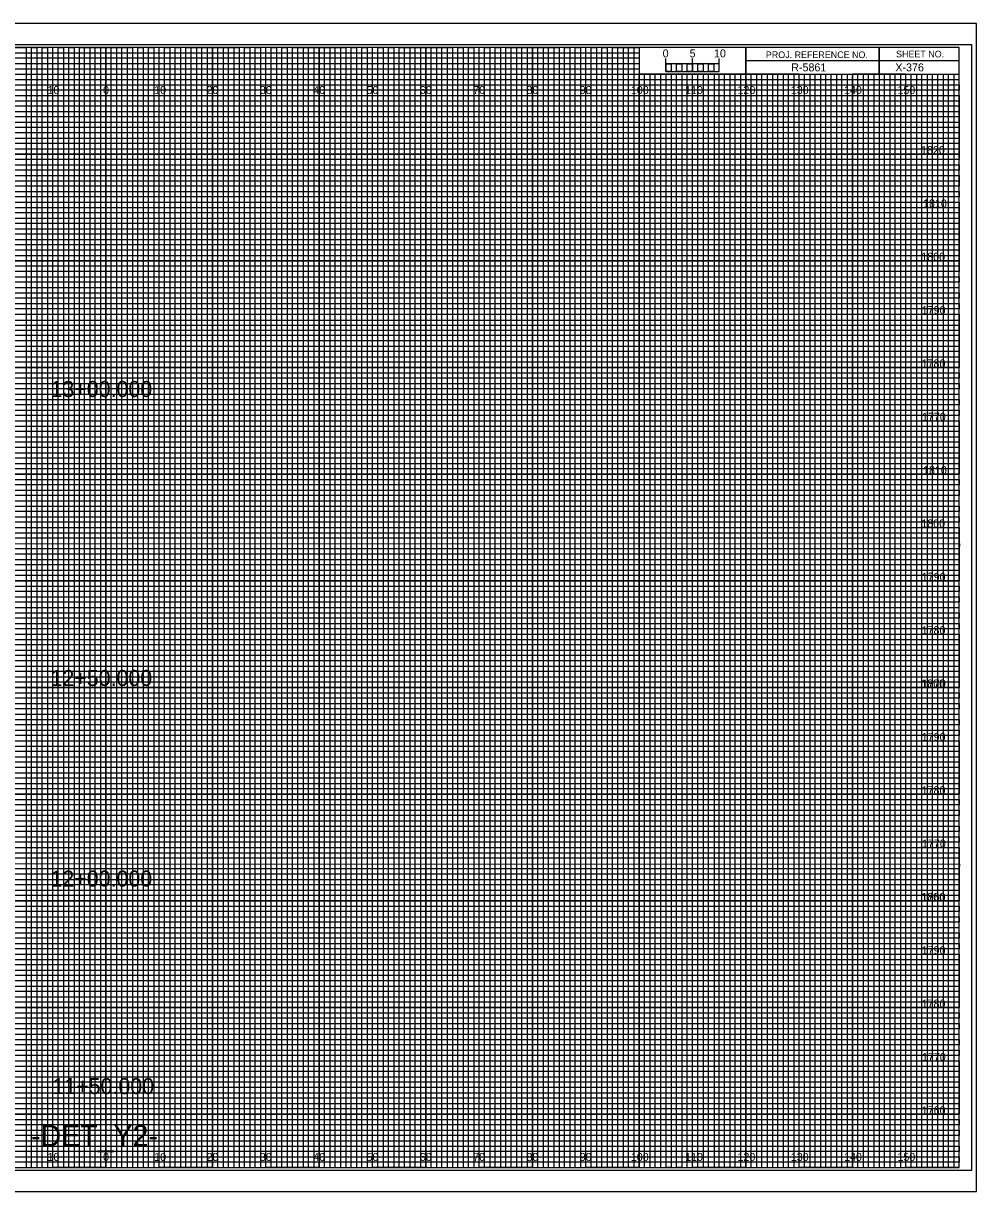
# Model space of a CAD drawing. Extents: x -13 to 323, y -5 to 874.
# Drawn here: x 144.5 to 323.3, y 215.5 to 434.5 of the extents above; entities that cross this region are included whole.
import ezdxf

# ---------------------------------------------------------------- set-up
doc = ezdxf.new("R2010")
doc.units = 0
for name, color, linetype in [('Prop Horizontal Alignment', 7, 'Continuous'), ('Prop XS Alignment Label', 7, 'Continuous'), ('Prop XS Bar Scale Labels', 7, 'Continuous'), ('Prop XS Earthwork Shape', 7, 'Continuous'), ('Prop XS Project Number', 7, 'Continuous'), ('Prop XS Sheet Number', 7, 'Continuous'), ('Raster_Level_0', 7, 'Continuous'), ('Scratch_Level_3', 7, 'Continuous'), ('Sheet Cross Section CELL', 7, 'Continuous'), ('Sheet Cross Section Grid Middle CELL', 7, 'Continuous'), ('Sheet Cross Section Grid Minor 1 CELL', 7, 'Continuous'), ('Sheet Cross Section Grid Minor 2 CELL', 7, 'Continuous'), ('Sheet Cross Section Scale CELL', 7, 'Continuous'), ('Sheet Cutting Line CELL', 7, 'Continuous'), ('Sheet DOT Grid CELL', 7, 'Continuous'), ('Sheet Plot Border Inside CELL', 7, 'Continuous'), ('Sheet Plot Border Outside CELL', 7, 'Continuous')]:
    doc.layers.add(name, color=color, linetype=linetype)

msp = doc.modelspace()

# ---------------------------------------------------------------- linework, layer by layer
at = {"layer": 'Prop XS Earthwork Shape'}
for p, q in [((150, 430), (140, 430)), ((150, 220), (150, 430)), ((170, 430), (160, 430)), ((160, 430), (160, 220)), ((170, 220), (170, 430)), ((190, 430), (180, 430)), ((180, 430), (180, 220)), ((190, 220), (190, 430)), ((210, 430), (200, 430)), ((200, 430), (200, 220)), ((210, 220), (210, 430)), ((230, 430), (220, 430)), ((220, 430), (220, 220)), ((230, 220), (230, 430)), ((250, 430), (240, 430)), ((240, 430), (240, 220)), ((250, 220), (250, 430)), ((260, 430), (260, 220)), ((270, 220), (270, 425)), ((290, 425), (280, 425)), ((280, 425), (280, 220)), ((290, 220), (290, 425)), ((310, 425), (300, 425)), ((300, 425), (300, 220)), ((310, 220), (310, 425)), ((160, 220), (150, 220)), ((180, 220), (170, 220)), ((200, 220), (190, 220)), ((220, 220), (210, 220)), ((240, 220), (230, 220)), ((260, 220), (250, 220)), ((280, 220), (270, 220)), ((300, 220), (290, 220)), ((320, 220), (310, 220)), ((320, 220), (320, 220))]:
    msp.add_line(p, q, dxfattribs=at)
for points in [[(0, 420), (320, 420), (320, 410), (0, 410)], [(0, 400), (320, 400), (320, 390), (0, 390)], [(0, 380), (320, 380), (320, 370), (0, 370)], [(0, 360), (320, 360), (320, 350), (0, 350)], [(0, 340), (320, 340), (320, 330), (0, 330)], [(0, 320), (320, 320), (320, 310), (0, 310)], [(0, 300), (320, 300), (320, 290), (0, 290)], [(0, 280), (320, 280), (320, 270), (0, 270)], [(0, 260), (320, 260), (320, 250), (0, 250)], [(0, 240), (320, 240), (320, 230), (0, 230)]]:
    msp.add_lwpolyline(points, dxfattribs=at)
at = {"layer": 'Sheet Cross Section CELL'}
for p, q in [((305, 430), (305, 425)), ((305, 425), (305, 430)), ((280, 427.5), (280, 425)), ((320, 427.49), (280, 427.49)), ((280, 425), (320, 425))]:
    msp.add_line(p, q, dxfattribs=at)
for points in [[(320, 430), (0, 430), (0, 220), (320, 220)], [(280, 430), (260, 430), (260, 425.03), (280, 425.03)], [(320, 430), (280, 430), (280, 425), (320, 425)]]:
    msp.add_lwpolyline(points, close=True, dxfattribs=at)
at = {"layer": 'Sheet Cross Section Grid Middle CELL'}
for points in [[(135, 430), (145, 430), (145, 220), (155, 220), (155, 430), (165, 430), (165, 220), (175, 220), (175, 430), (185, 430), (185, 220), (195, 220), (195, 430), (205, 430), (205, 220), (215, 220), (215, 430), (225, 430), (225, 220), (235, 220), (235, 430), (245, 430), (245, 220), (255, 220), (255, 430), (259.93, 430), (260, 430), (260, 425), (264.99, 425), (264.99, 220), (275, 220), (275, 425), (285, 425), (285, 220), (295, 220), (295, 425), (305, 425), (305, 220), (315, 220), (315, 425)], [(0, 425), (275, 425)], [(0, 405), (320, 405), (320, 415), (0, 415)], [(0, 385), (320, 385), (320, 395), (0, 395)], [(0, 365), (320, 365), (320, 375), (0, 375)], [(0, 345), (320, 345), (320, 355), (0, 355)], [(0, 325), (320, 325), (320, 335), (0, 335)], [(0, 305), (320, 305), (320, 315), (0, 315)], [(0, 285), (320, 285), (320, 295), (0, 295)], [(0, 265), (320, 265), (320, 275), (0, 275)], [(0, 245), (320, 245), (320, 255), (0, 255)], [(0, 225), (320, 225), (320, 235), (0, 235)]]:
    msp.add_lwpolyline(points, dxfattribs=at)
at = {"layer": 'Sheet Cross Section Grid Minor 1 CELL'}
for p, q in [((0, 429), (260, 429)), ((260, 427.98), (0, 427.98)), ((260, 429), (260, 427.98)), ((0, 427), (260, 427)), ((260, 425.89), (0, 425.89)), ((260, 427), (260, 425.89)), ((0, 424), (320, 424))]:
    msp.add_line(p, q, dxfattribs=at)
for points in [[(0, 423), (270, 423), (320, 423), (320, 422), (0, 422)], [(0, 421), (320, 421), (320, 419), (0, 419)], [(0, 418), (320, 418), (320, 417), (0, 416.98)], [(0, 416), (320, 416), (320, 414), (0, 414)], [(0, 413), (320, 413), (320, 412), (0, 412)], [(0, 411), (320, 411), (320, 409), (0, 409)], [(0, 408), (320, 408), (320, 407), (0, 407)], [(0, 406), (320, 406), (320, 404), (0, 404)], [(0, 403), (320, 403), (320, 402), (0, 402)], [(0, 401), (320, 401), (320, 399), (0, 399)], [(0, 398), (320, 398), (320, 397), (0, 397)], [(0, 396), (320, 396), (320, 393.95), (320, 393), (320, 392), (0, 392)], [(0, 394), (320, 394), (320, 393), (0, 393)], [(0, 391), (320, 391), (320, 389), (0, 389.03)], [(0, 389.03), (320, 389), (320, 388), (0, 388)], [(0, 387), (320, 387), (320, 386), (0, 386)], [(0, 384), (320, 384), (320, 383), (0, 383)], [(0, 382), (320, 382), (320, 381), (0, 381)], [(-0.07, 378.89), (320, 378.89), (320, 377.88), (-0.07, 377.88)], [(0, 377), (320, 377), (320, 376), (0, 376)], [(0, 374), (320, 374), (320, 373), (0, 373)], [(0, 372), (320, 372), (320, 371), (0, 371)], [(0, 369), (320, 369), (320, 368), (0, 368)], [(0, 367), (320, 367), (320, 366), (0, 366)], [(0, 364), (320, 364), (320, 363), (0, 363)], [(0, 362), (320, 362), (320, 361), (0, 361)], [(0, 359), (320, 359), (319.99, 357.98), (0, 358)], [(0, 357), (320, 357), (320, 356), (0, 356)], [(0, 354), (320, 354), (320, 353), (0, 353)], [(0, 352), (320, 352), (320, 351), (0, 351)], [(0, 349), (320, 349), (320, 348), (0, 348)], [(0, 347), (320, 347), (320, 346), (0, 346)], [(0, 344), (320, 344), (320, 343), (0, 343)], [(0, 342), (320, 342), (320, 341), (0, 341)], [(0, 339), (320, 339), (320, 338), (0, 338)], [(0, 336.99), (320.07, 336.91), (320, 336), (0, 336)], [(0, 334), (320, 334), (320, 333), (0, 333)], [(0, 332), (320, 332), (320, 331), (0, 331)], [(0, 329), (320, 329), (320, 328), (0, 328)], [(0, 327), (320, 327), (320, 326), (0, 326)], [(0, 324), (320, 324), (320, 323), (0, 323)], [(0, 322), (320, 322), (320, 321), (0, 321)], [(0, 319), (320, 319), (320, 318), (0, 318)], [(0, 317), (320, 317), (320, 316), (0, 316)], [(0, 314), (320, 314), (320, 313), (0, 313)], [(0, 312), (320, 312), (320, 311), (0, 311)], [(0, 309), (320, 309), (320, 308), (0, 308)], [(0, 307), (320, 307), (320, 306), (0, 306)], [(0, 304), (320, 304), (320, 303), (0, 303)], [(0, 302), (320, 302), (320, 301), (0, 301)], [(0, 299), (320, 299), (319.99, 297.98), (0, 298)], [(0, 297), (320, 297), (320, 296), (0, 296)], [(0, 294), (320, 294), (320, 293), (0, 293)], [(0, 292), (320, 292), (320, 291), (0, 291)], [(0, 289), (320, 289), (320, 288), (0, 288)], [(0, 287), (320, 287), (320, 286), (0, 286)], [(0, 284), (320, 284), (320, 283), (0, 283)], [(0, 282), (320, 282), (320, 281), (0, 281)], [(0, 279), (320, 279), (320, 278), (0, 278)], [(0, 276.99), (320.07, 276.91), (320, 276), (0, 276)], [(0, 274), (320, 274), (320, 273), (0, 273)], [(0, 272), (320, 272), (320, 271), (0, 271)], [(0, 269), (320, 269), (320, 268), (0, 268)], [(0, 267), (320, 267), (320, 266), (0, 266)], [(0, 264), (320, 264), (320, 263), (0, 263)], [(0, 262), (320, 262), (320, 261), (0, 261)], [(0, 259), (320, 259), (320, 258), (0, 258)], [(0, 257), (320, 257), (320, 256), (0, 256)], [(0, 254), (320, 254), (320, 253), (0, 253)], [(0, 252), (320, 252), (320, 251), (0, 251)], [(0, 249), (320, 249), (320, 248), (0, 248)], [(0, 247), (320, 247), (320, 246), (0, 246)], [(0, 244), (320, 244), (320, 243), (0, 243)], [(0, 242), (320, 242), (320, 241), (0, 241)], [(0, 239), (320, 239), (320, 238), (0, 238)], [(0, 237), (320, 237), (320, 236), (0, 236)], [(0, 234), (320, 234), (320, 233), (0, 233)], [(0, 232), (320, 232), (320, 231), (0, 231)], [(0, 229), (320, 229), (320, 228), (0, 228)], [(0, 227), (320, 227), (320, 226), (0, 226)], [(0, 224), (320, 224), (320, 223), (0, 223)], [(0, 222), (320, 222), (320, 221), (0, 221)]]:
    msp.add_lwpolyline(points, dxfattribs=at)
at = {"layer": 'Sheet Cross Section Grid Minor 2 CELL'}
for p, q in [((267, 425), (266.01, 425)), ((266.01, 425), (266.01, 220)), ((267, 220), (267, 425)), ((269, 425), (268, 425)), ((268, 425), (268, 220)), ((269, 220), (269, 425)), ((266.01, 220), (265, 220)), ((268, 220), (267, 220))]:
    msp.add_line(p, q, dxfattribs=at)
for points in [[(145, 220), (146, 220), (146, 430), (147, 430), (147, 220)], [(147, 220), (148, 220), (148, 430), (149, 430), (149, 220)], [(150, 220), (151, 220), (151, 430), (152, 430), (152, 220)], [(152, 220), (153, 220), (153, 430), (154, 430), (154, 220)], [(155, 220), (156, 220), (156, 430), (157, 430), (157, 220)], [(157, 220), (158, 220), (158, 430), (159, 430), (159, 220)], [(160, 220), (161, 220), (161, 430), (162, 430), (162, 220)], [(162, 220), (163, 220), (163, 430), (164, 430), (164, 220)], [(165, 220), (166, 220), (166, 430), (167, 430), (167, 220)], [(167, 220), (168, 220), (168, 430), (169, 430), (169, 220)], [(170, 220), (171, 220), (171, 430), (172, 430), (172, 220)], [(172, 220), (173, 220), (173, 430), (174, 430), (174, 220)], [(175, 220), (176, 220), (176, 430), (177, 430), (177, 220)], [(177, 220), (178, 220), (178, 430), (179, 430), (179, 220)], [(180, 220), (181, 220), (181, 430), (182, 430), (182, 220)], [(182, 220), (183, 220), (183, 430), (184, 430), (184, 220)], [(185, 220), (186, 220), (186, 430), (187, 430), (187, 220)], [(187, 220), (188, 220), (188, 430), (189, 430), (189, 220)], [(190, 220), (191, 220), (191, 430), (192, 430), (192, 220)], [(192, 220), (193, 220), (193, 430), (194, 430), (194, 220)], [(195, 220), (196, 220), (196, 430), (197, 430), (197, 220)], [(197, 220), (198, 220), (198, 430), (199, 430), (199, 220)], [(200, 220), (201, 220), (201, 430), (202, 430), (202, 220)], [(202, 220), (203, 220), (203, 430), (204, 430), (204, 220)], [(205, 220), (206, 220), (206, 430), (207, 430), (207, 220)], [(207, 220), (208, 220), (208, 430), (209, 430), (209, 220)], [(210, 220), (211, 220), (211, 430), (212, 430), (212, 220)], [(212, 220), (213, 220), (213, 430), (214, 430), (214, 220)], [(215, 220), (216, 220), (216, 430), (217, 430), (217, 220)], [(217, 220), (218, 220), (218, 430), (219, 430), (219, 220)], [(220, 220), (221, 220), (221, 430), (222, 430), (222, 220)], [(222, 220), (223, 220), (223, 430), (224, 430), (224, 220)], [(225, 220), (226, 220), (226, 430), (227, 430), (227, 220)], [(227, 220), (228, 220), (228, 430), (229, 430), (229, 220)], [(230, 220), (231, 220), (231, 430), (232, 430), (232, 220)], [(232, 220), (233, 220), (233, 430), (234, 430), (234, 220)], [(235, 220), (236, 220), (236, 430), (237, 430), (237, 220)], [(237, 220), (238, 220), (238, 430), (239, 430), (239, 220)], [(240, 220), (241, 220), (241, 430), (242, 430), (242, 220)], [(242, 220), (243, 220), (243, 430), (244, 430), (244, 220)], [(245, 220), (246, 220), (246, 430), (247, 430), (247, 220)], [(247, 220), (248, 220), (248, 430), (249, 430), (249, 220)], [(250, 220), (251, 220), (251, 430), (252, 430), (252, 220)], [(252, 220), (253, 220), (253, 430), (254, 430), (254, 220)], [(255, 220), (256, 220), (256, 430), (257, 430), (257, 220)], [(257, 220), (258, 220), (258, 430), (259, 430), (259, 220)], [(260, 220), (261, 220), (261, 425), (262.02, 425), (262.02, 220)], [(262, 220), (263, 220), (263, 425), (263.99, 425), (263.99, 220)], [(270, 220), (270.98, 220), (270.98, 425), (272, 425), (272, 220)], [(272, 220), (273, 220), (273, 425), (274.05, 425), (274.05, 220)], [(275, 220), (276, 220), (276, 425), (277, 425), (277, 220)], [(277, 220), (278, 220), (278, 425), (279, 425), (279, 220)], [(280, 220), (281, 220), (281, 425), (282, 425), (282, 220)], [(282, 220), (283, 220), (283, 425), (284, 425), (284, 220)], [(285, 220), (286, 220), (286, 425), (287, 425), (287, 220)], [(287, 220), (288, 220), (288, 425), (289, 425), (289, 220)], [(290, 220), (291, 220), (291, 425), (292, 425), (292, 220)], [(292, 220), (293, 220), (293, 425), (294, 425), (294, 220)], [(295, 220), (296, 220), (296, 425), (297, 425), (297, 220)], [(297, 220), (298, 220), (298, 425), (299, 425), (299, 220)], [(300, 220), (301, 220), (301, 425), (302, 425), (302, 220)], [(302, 220), (303, 220), (303, 425), (304, 425), (304, 220)], [(305, 220), (306, 220), (306, 425), (307, 425), (307, 220)], [(307, 220), (308, 220), (308, 425), (309, 425), (309, 220)], [(310, 220), (311, 220), (311, 425), (312, 425), (312, 220)], [(312, 220), (313, 220), (313, 425), (314, 425), (314, 220)], [(315, 220), (316, 220), (316, 425), (317, 425), (317, 220)], [(317, 220), (318, 220), (318, 425), (319, 425), (319, 220)]]:
    msp.add_lwpolyline(points, dxfattribs=at)
at = {"layer": 'Sheet Cross Section Scale CELL'}
for p, q in [((265, 425.49), (265, 427.9)), ((265, 426.9), (265, 427.9)), ((270, 425.49), (270, 427.9)), ((275, 425.49), (275, 427.9)), ((275, 426.9), (275, 427.9))]:
    msp.add_line(p, q, dxfattribs=at)
for points in [[(275, 426.9), (265, 426.9), (265, 425.49), (275, 425.49)], [(265, 426.9), (266, 426.9), (266, 425.49), (265, 425.49)], [(267, 426.9), (268, 426.9), (268, 425.49), (267, 425.49)], [(269, 426.9), (270, 426.9), (270, 425.49), (269, 425.49)], [(271, 426.9), (272, 426.9), (272, 425.49), (271, 425.49)], [(273, 426.9), (274, 426.9), (274, 425.49), (273, 425.49)]]:
    msp.add_lwpolyline(points, close=True, dxfattribs=at)
at = {"layer": 'Sheet Cutting Line CELL'}
for p, q in [((323.3, 434.5), (-13.4, 434.5)), ((-13.4, 215.5), (323.3, 215.5))]:
    msp.add_line(p, q, dxfattribs=at)
at = {"layer": 'Sheet DOT Grid CELL'}
for p, q in [((150, 220), (150, 430)), ((160, 220), (160, 430)), ((170, 220), (170, 430)), ((180, 220), (180, 430)), ((190, 220), (190, 430)), ((200, 220), (200, 430)), ((210, 220), (210, 430)), ((220, 220), (220, 430)), ((230, 220), (230, 430)), ((240, 220), (240, 430)), ((250, 220), (250, 430)), ((260, 220), (260, 424.69)), ((270, 220), (270, 424.69)), ((280, 220), (280, 424.69)), ((290, 220), (290, 424.69)), ((300, 220), (300, 424.69)), ((310, 220), (310, 424.69)), ((0, 420), (320, 420)), ((0, 410), (320, 410)), ((0, 400), (320, 400)), ((0, 390), (320, 390)), ((0, 380), (320, 380)), ((0, 370), (320, 370)), ((0, 360), (320, 360)), ((0, 350), (320, 350)), ((0, 340), (320, 340)), ((0, 330), (320, 330)), ((0, 320), (320, 320)), ((0, 310), (320, 310)), ((0, 300), (320, 300)), ((0, 290), (320, 290)), ((0, 280), (320, 280)), ((0, 270), (320, 270)), ((0, 260), (320, 260)), ((0, 250), (320, 250)), ((0, 240), (320, 240)), ((0, 230), (320, 230))]:
    msp.add_line(p, q, dxfattribs=at)
at = {"layer": 'Sheet Plot Border Inside CELL'}
msp.add_lwpolyline([(-10.8, 219.5), (322.4, 219.5), (322.4, 430.5), (-10.8, 430.5)], close=True, dxfattribs=at)
at = {"layer": 'Sheet Plot Border Outside CELL'}
msp.add_lwpolyline([(-13.4, 215.5), (323.3, 215.5), (323.3, 434.5), (-13.4, 434.5)], close=True, dxfattribs=at)

# ---------------------------------------------------------------- texts
at = {"layer": 'Prop Horizontal Alignment'}
for s, p in [('13+00.000', (149.59, 364.46)), ('12+50.000', (149.59, 310.29)), ('12+00.000', (149.59, 272.68)), ('11+50.000', (149.95, 233.78))]:
    msp.add_text(s, height=3, dxfattribs=at).set_placement(p)
at = {"layer": 'Prop XS Alignment Label'}
msp.add_text('-DET_Y2-', height=4, dxfattribs=at).set_placement((145.96, 224))
at = {"layer": 'Prop XS Bar Scale Labels'}
for s, p in [('5', (269.47, 428.12)), ('10', (274.04, 428.12))]:
    msp.add_text(s, height=1.5, dxfattribs=at).set_placement(p)
at = {"layer": 'Prop XS Project Number'}
msp.add_text('R-5861', height=1.5, dxfattribs=at).set_placement((288.53, 425.5))
at = {"layer": 'Prop XS Sheet Number'}
msp.add_text('X-376', height=1.5, dxfattribs=at).set_placement((308.05, 425.5))
at = {"layer": 'Raster_Level_0'}
for s, p in [('10', (149.04, 421.25)), ('0', (159.45, 421.25)), ('0', (159.45, 421.25)), ('10', (169.04, 421.25)), ('20', (178.86, 421.25)), ('30', (188.86, 421.25)), ('40', (198.86, 421.25)), ('50', (208.86, 421.25)), ('60', (218.86, 421.25)), ('70', (228.86, 421.25)), ('80', (238.86, 421.25)), ('90', (248.86, 421.25)), ('100', (258.44, 421.25)), ('110', (268.62, 421.25)), ('120', (278.44, 421.25)), ('130', (288.44, 421.25)), ('140', (298.44, 421.25)), ('150', (308.44, 421.25)), ('10', (149.04, 221.25)), ('0', (159.45, 221.25)), ('0', (159.45, 221.25)), ('10', (169.04, 221.25)), ('20', (178.86, 221.25)), ('30', (188.86, 221.25)), ('40', (198.86, 221.25)), ('50', (208.86, 221.25)), ('60', (218.86, 221.25)), ('70', (228.86, 221.25)), ('80', (238.86, 221.25)), ('90', (248.86, 221.25)), ('100', (258.44, 221.25)), ('110', (268.62, 221.25)), ('120', (278.44, 221.25)), ('130', (288.44, 221.25)), ('140', (298.44, 221.25)), ('150', (308.44, 221.25))]:
    msp.add_text(s, height=1.5, dxfattribs=at).set_placement(p)
at = {"layer": 'Scratch_Level_3'}
for s, p in [('1820', (312.87, 410)), ('1810', (313.25, 400)), ('1800', (312.92, 390)), ('1790', (313, 380)), ('1780', (312.98, 370)), ('1770', (313.04, 360)), ('1810', (313.25, 350)), ('1800', (312.92, 340)), ('1790', (313, 330)), ('1780', (312.98, 320)), ('1800', (312.92, 310)), ('1770', (313.04, 310)), ('1790', (313, 300)), ('1780', (312.98, 290)), ('1770', (313.04, 280)), ('1800', (312.92, 270)), ('1760', (313, 270)), ('1790', (313, 260)), ('1780', (312.98, 250)), ('1770', (313.04, 240)), ('1760', (313, 230))]:
    msp.add_text(s, height=1.5, dxfattribs=at).set_placement(p)
at = {"layer": 'Sheet Cross Section CELL'}
for s, p in [('PROJ. REFERENCE NO.', (283.77, 427.99)), ('SHEET NO.', (308.19, 428.12))]:
    msp.add_text(s, height=1.25, dxfattribs=at).set_placement(p)
at = {"layer": 'Sheet Cross Section Scale CELL'}
msp.add_text('0', height=1.5, dxfattribs=at).set_placement((264.41, 428.12))

doc.saveas('drawing.dxf')
